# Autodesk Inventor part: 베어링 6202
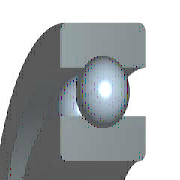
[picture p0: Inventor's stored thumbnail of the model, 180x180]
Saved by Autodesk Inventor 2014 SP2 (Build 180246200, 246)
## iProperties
Created: 2015-12
Part Number: 베어링 6202
Material: 강철, 연강
Description: 깊은 그루브 볼 베어링
Document SubType Name: Modeling
Standard: KS B 2023
Designer: mdu
Standards Organization: KS
Language: ko-KR
Size Designation: 6202 - 15 x 35 x 11
Categories: <MemberInstance><Categories><Category DisplayName="샤프트 부품" InternalName="7f7aeb1f-a693-4053-b835-cee3144e0d98" Mnemonic="SHFT"><Category DisplayName="베어링" Inter
Density: 7.86 g/cm^3
Mass: 45.8725 g
Surface Area: 51.5584 cm^2
Volume: 5.83619 cm^3
Appearance: 노란색
Company: 한국ATC센터
IsCustomPart: 1
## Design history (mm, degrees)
sketch "스케치" dims "d0" = 5.2 (= -0.26 x WD + 0.26 x BD)
  geometry: L1 (2.9, 12.5)-(8.1, 12.5); L2 (5.5, 12.5)-(5.5, 9.9); L3 (5.5, 12.5)-(5.5, 15.1); L4 (3.568, 10.76)-(0, 10.76); L5 (0, 7.5)-(11, 7.5); L6 (3.568, 14.24)-(0, 14.24); L7 (0, 17.5)-(11, 17.5); L8 (11, 7.5)-(11, 10.76); L9 (7.432, 10.76)-(11, 10.76); L10 (7.432, 14.24)-(11, 14.24); L11 (11, 17.5)-(11, 14.24); L12 (-1.4, 0)-(8.4, 0) reference; L13 (0, -0.3)-(0, 5.3) reference
  constraints: 22 end point, 4 point on line, 2 collinear, 2 perpendicular, 2 symmetric about line, 1 midpoint, 1 parallel, 14 other
  dimensions: "d9" = 15 diameter of L5 L12 (= WD); "d11" = 35 diameter of L7 L12 (= BD); "d12" = 11 distance between parallel lines of L8 L13 (= KB); "d13" = 21.52 diameter of L9 L12 (= 0.326 x BD + 0.674 x WD)
revolve "본체" stored, may be unused: angle "d6" = 90 deg
revolve "볼" stored, may be unused: angle "d7" = 90 deg
pattern_circular "IDS_ARRAYBALL[SIMPL:T]" dims angle "d3" = 360 deg
body "Solid1"
fillet "모깎기1" dims "d1" = 0.6 (= KRS)
other parameters: "WD" = 15 [user parameter; used in 5 equation terms], "BD" = 35 [user parameter; used in 5 equation terms], "KB" = 11 [user parameter; used in 1 equation term], "KRS" = 0.6 [user parameter; used in 1 equation term], "d4" = 0, "d5" = 0, "d8" = 0, "d14" = 0, "d15" = 0, "BBA" = 0 [user parameter], "BC0" = 3750000 [user parameter], "BC" = 7800000 [user parameter], "BR" = 17.5 (= 0.5 x BD) [user parameter], "WR" = 7.5 (= 0.5 x WD) [user parameter]
